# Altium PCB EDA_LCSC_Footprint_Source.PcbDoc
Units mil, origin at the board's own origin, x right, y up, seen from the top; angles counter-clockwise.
Board outline 4500 x 2500 mil, 2 copper layers (Top Layer, Bottom Layer), stack 62.2 mil thick; 64 components, 41 nets, 178 pads, 0 vias.
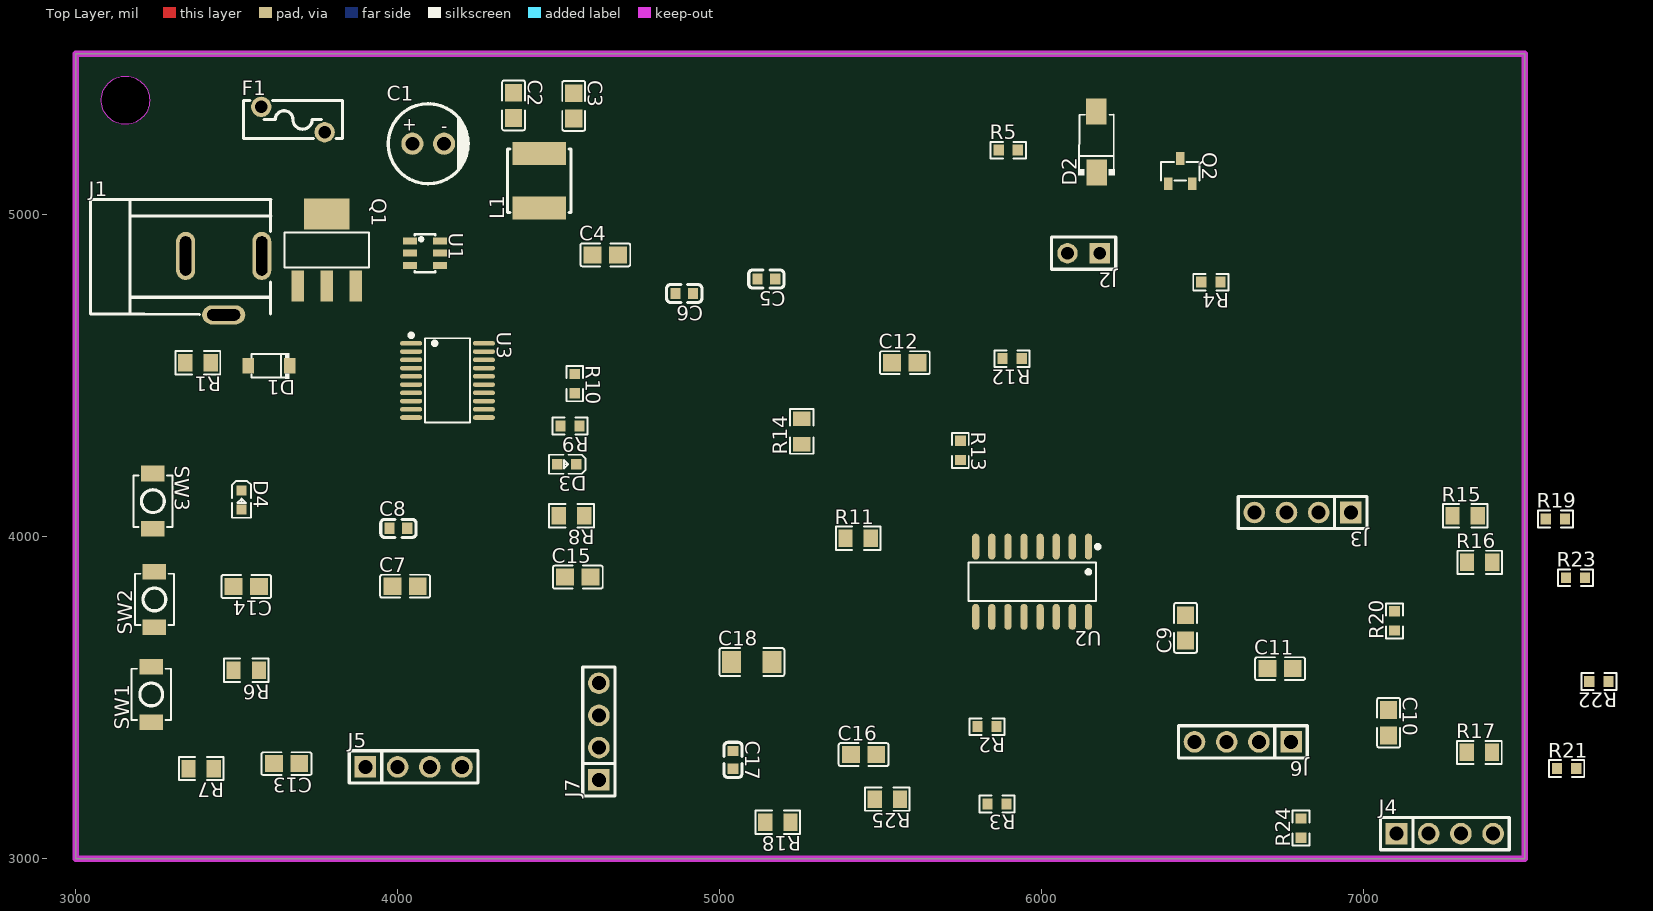
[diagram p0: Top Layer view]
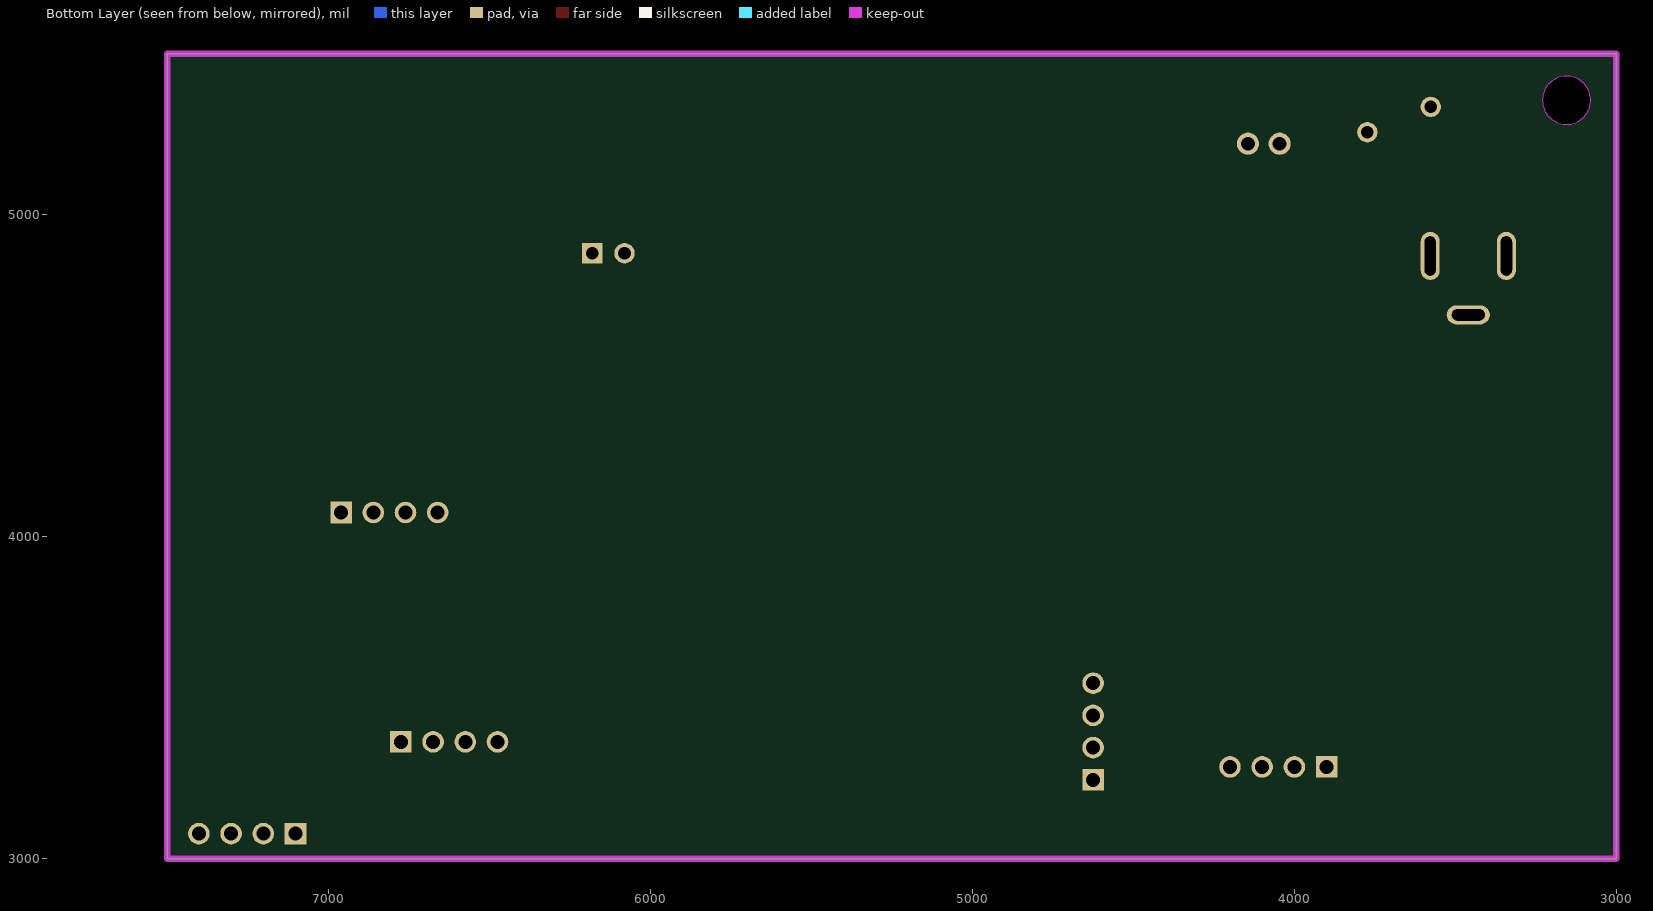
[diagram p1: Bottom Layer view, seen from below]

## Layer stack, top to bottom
Top Solder Mask Layer: solder mask 0.4, Dk 3.3
Top Layer: signal copper 1.4
Dielectric1: surface 59.4, FR4, Dk 4.5
Bottom Layer: signal copper 1.4
Bottom Solder Mask Layer: solder mask 0.4, Dk 3.3

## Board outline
3000,5500 3000,3000 7500,3000 7500,5500
cut-out: 3230,5355 3229.6,5347.3 3228.4,5339.7 3226.4,5332.2 3223.7,5325 3220.3,5318.1 3216.1,5311.5 3211.3,5305.5 3205.9,5300 3200,5295 3193.6,5290.7 3186.8,5287.1 3179.6,5284.2 3172.2,5282 3164.6,5280.6 3156.9,5280 3149.2,5280.2 3141.6,5281.2 3134,5283 3126.7,5285.5 3119.8,5288.8 3113.1,5292.8 3107,5297.4 3101.3,5302.7 3096.2,5308.5 3091.7,5314.7 3087.9,5321.5 3084.8,5328.5 3082.5,5335.9 3080.9,5343.5 3080.1,5351.1 3080.1,5358.9 3080.9,5366.5 3082.5,5374.1 3084.8,5381.5 3087.9,5388.5 3091.7,5395.3 3096.2,5401.5 3101.3,5407.3 3107,5412.6 3113.1,5417.2 3119.8,5421.2 3126.7,5424.5 3134,5427 3141.6,5428.8 3149.2,5429.8 3156.9,5430 3164.6,5429.4 3172.2,5428 3179.6,5425.8 3186.8,5422.9 3193.6,5419.3 3200,5415 3205.9,5410 3211.3,5404.5 3216.1,5398.5 3220.3,5391.9 3223.7,5385 3226.4,5377.8 3228.4,5370.3 3229.6,5362.7

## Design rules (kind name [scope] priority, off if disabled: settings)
BoardOutlineClearance copperThickness1oz [All] p0: genericclearance=10 ignorepadtopadclearanceinfootprint=FALSE except(0: Arc-SplitContinuation Track-SplitContinuation SMDPad-SplitContinuation THPad-SplitContinuation Via-SplitContinuation Fill-SplitContinuation Poly-SplitContinuation Region-SplitContinuation Text-SplitContinuation)
BoardOutlineClearance copperThickness2oz [All] p0: genericclearance=10 ignorepadtopadclearanceinfootprint=FALSE except(0: Arc-SplitContinuation Track-SplitContinuation SMDPad-SplitContinuation THPad-SplitContinuation Via-SplitContinuation Fill-SplitContinuation Poly-SplitContinuation Region-SplitContinuation Text-SplitContinuation)
BoardOutlineClearance Plane_innerPlane [All] p0: genericclearance=10 ignorepadtopadclearanceinfootprint=FALSE except(0: Arc-SplitContinuation Track-SplitContinuation SMDPad-SplitContinuation THPad-SplitContinuation Via-SplitContinuation Fill-SplitContinuation Poly-SplitContinuation Region-SplitContinuation Text-SplitContinuation)
BoardOutlineClearance Copper_copperRegion [All] p0: genericclearance=10 ignorepadtopadclearanceinfootprint=FALSE except(0: Arc-SplitContinuation Track-SplitContinuation SMDPad-SplitContinuation THPad-SplitContinuation Via-SplitContinuation Fill-SplitContinuation Poly-SplitContinuation Region-SplitContinuation Text-SplitContinuation)
BoardOutlineClearance otherClearance [All] p0: genericclearance=10 ignorepadtopadclearanceinfootprint=FALSE except(0: Arc-SplitContinuation Track-SplitContinuation SMDPad-SplitContinuation THPad-SplitContinuation Via-SplitContinuation Fill-SplitContinuation Poly-SplitContinuation Region-SplitContinuation Text-SplitContinuation)
Clearance copperThickness1oz [All] p1: gap=7 ignorepadtopadclearanceinfootprint=FALSE
Clearance copperThickness2oz [All] p1: gap=7 ignorepadtopadclearanceinfootprint=FALSE
Clearance Plane_innerPlane [All] p1: gap=7 ignorepadtopadclearanceinfootprint=FALSE
Clearance Copper_copperRegion [All] p1: gap=7 ignorepadtopadclearanceinfootprint=FALSE
Clearance otherClearance [All] p1: gap=7 ignorepadtopadclearanceinfootprint=FALSE
DiffPairsRouting differentialPair [All] p1: maxuncoupledlength=10 minlimit=5.9843 maxlimit=Infinity mostfreqgap=5.9843 toplayer_minwidth=5 toplayer_prefwidth=10 toplayer_maxwidth=100 bottomlayer_minwidth=5 bottomlayer_prefwidth=10 bottomlayer_maxwidth=100
PasteMaskExpansion pasteMaskExpansion [All] p1: expansion=0
PlaneConnect innerPlane [All] p1: planeconnectstyle=Relief reliefexpansion=20 reliefentries=4 reliefconductorwidth=10 reliefairgap=10
PolygonConnect copperRegion [All] p1: connectstyle=Relief reliefentries=4 reliefconductorwidth=10 polygonreliefangle="90 Angle" airgapwidth=10
RoutingVias viaSize [All] p1: viastyle="Through Hole" holewidth=12.0078 minholewidth=11.811 maxholewidth=248.0314 width=12.0078 minwidth=11.811 maxwidth=248.0314
SolderMaskExpansion solderMaskExpansion [IsVia] p1: useseparateexpansions=TRUE expansion=-1000 expansionbottom=-1000
SolderMaskExpansion solderMaskExpansion [All] p2: useseparateexpansions=TRUE expansion=2.0079 expansionbottom=2.0079
Width copperThickness1oz [All] p1: maxlimit=100 minlimit=5 preferedwidth=10
Width copperThickness2oz [All] p1: maxlimit=100 minlimit=8 preferedwidth=10

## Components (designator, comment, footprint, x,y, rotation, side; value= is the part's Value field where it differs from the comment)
C1 "47uF" CAP-TH_BD6.3-P2.50-D0.6-FD 4095,5220 r0 top
C2 "10uF" C0805#1 4360.2,5338.9 r270 top
C3 "100nF" C0805#1 4546.9,5337.5 r270 top
C4 "100nF" C0805#2 4645,4875 r0 top
C5 "22uF" C0603#1 5145,4800 r180 top
C6 "22uF" C0603#1 4890,4755 r180 top
C7 "100nF" C0805#2 4023.1,3846 r0 top
C8 "4.7uF" C0603#2 4002.5,4025.6 r0 top
C9 "100nF" C0805#2 6446.6,3716.6 r90 top
C10 "100nF" C0805#3 7077.1,3422.3 r270 top
C11 "100nF" C0805#2 6740,3590 r0 top
C12 "100nF" C0805#2 5575,4540 r0 top
C13 "100nF" C0805#2 3655,3295 r180 top
C14 "100nF" C0805#2 3530,3845 r180 top
C15 "100nF" C0805#3 4559.6,3874.5 r0 top
C16 "100nF" C0805#2 5446.9,3323.1 r0 top
C17 "10uF" C0603#2 5041.5,3306.8 r270 top
C18 "220uF" C1206 5099.9,3610.6 r0 top
D1 "BZT52C10" SOD-123_L2.7-W1.6-LS3.7-RD 3600,4530 r180 top
D2 "SS16" SMA_L4.3-W2.6-LS5.0-RD 6170,5225 r90 top
D3 "FC-1608G1-520" LED0603-RD 4525,4225 r180 top
D4 "XL-1608SURC-06" LED0603-RD_RED 3515.3,4113.6 r270 top
F1 "RL60-050" FUSE-TH_L7.8-W3.0-P5.10-D0.5-S2.00 3675,5295 r0 top
J1 "DC005-T25" DC-IN-TH_DC-005-20A-1 3460,4780 r0 top
J2 "LAIL-PZ2.54-2P-L" CONN-TH_LAIL-PZ2.54-2P-L 6130,4880 r180 top
J3 "HX PZ2.54-1x4P ZZ" HDR-TH_4P-P2.54-V-M 6810,4075 r180 top
J4 "HX PZ2.54-1x4P ZZ" HDR-TH_4P-P2.54-V-M 7251.6,3077.8 r0 top
J5 "HX PZ2.54-1x4P ZZ" HDR-TH_4P-P2.54-V-M 4050,3285 r0 top
J6 "HX PZ2.54-1x4P ZZ" HDR-TH_4P-P2.54-V-M 6624.4,3362.8 r180 top
J7 "HX PZ2.54-1x4P ZZ" HDR-TH_4P-P2.54-V-M 4625,3395 r90 top
L1 "3.9uH" IND-SMD_L5.0-W5.0_FNR50XXS 4440,5105 r90 top
Q1 "DMP6023LE-13" SOT-223-4_L6.5-W3.5-P2.30-LS7.0-BR 3780,4890 r270 top
Q2 "AO3400A" SOT-23-3_L2.9-W1.3-P1.90-LS2.4-BR 6430,5135 r270 top
R1 "47kΩ" R0805 3380,4540 r180 top
R2 "1kΩ" R0603#1 5830,3410 r180 top
R3 "1kΩ" R0603#2 5861,3169.9 r180 top
R4 "1kΩ" R0603#1 6525,4790 r180 top
R5 "100kΩ" R0603#2 5896,5200 r0 top
R6 "10kΩ" R0805 3530,3585 r180 top
R7 "10kΩ" R0805 3390,3280 r180 top
R8 "10kΩ" R0805 4540,4065 r180 top
R9 "1kΩ" R0603#2 4535.2,4343.3 r180 top
R10 "1kΩ" R0603#1 4550,4475 r270 top
R11 "10kΩ" R0805 5430,3995 r0 top
R12 "100kΩ" R0603#2 5907.9,4552.5 r180 top
R13 "100kΩ" R0603#1 5747.4,4267.9 r270 top
R14 "10kΩ" R0805 5254.6,4326.7 r90 top
R15 "10kΩ" R0805 7315,4065 r0 top
R16 "10kΩ" R0805 7360,3920 r0 top
R17 "10kΩ" R0805 7358.9,3330 r0 top
R18 "10kΩ" R0805 5180.6,3113.1 r180 top
R19 "1kΩ" R0603#1 7595,4055 r0 top
R20 "1kΩ" R0603#3 7095.6,3738.5 r90 top
R21 "1kΩ" R0603#1 7630,3280 r0 top
R22 "1kΩ" R0603#1 7730,3550 r180 top
R23 "1kΩ" R0603#3 7657.2,3872.4 r0 top
R24 "1kΩ" R0603#1 6805,3095 r90 top
R25 "10kΩ" R0805 5520.6,3185 r180 top
SW1 "TS-1088-AR02016" SW-SMD_L3.9-W3.0-P4.45 3235,3510 r90 top
SW2 "TS-1088-AR02016" SW-SMD_L3.9-W3.0-P4.45 3245,3805 r90 top
SW3 "TS-1088-AR02016" SW-SMD_L3.9-W3.0-P4.45 3240,4110 r270 top
U1 "AP63203WU-7" TSOT-26_L2.9-W1.6-P0.95-LS2.8-BL 4085,4880 r270 top
U2 "74HC4052D,652" SO-16_L9.9-W3.9-P1.27-LS6.0-BL 5970,3860 r180 top
U3 "STM32G030F6P6" TSSOP-20_L6.5-W4.4-P0.65-LS6.4-BL 4155,4485 r270 top

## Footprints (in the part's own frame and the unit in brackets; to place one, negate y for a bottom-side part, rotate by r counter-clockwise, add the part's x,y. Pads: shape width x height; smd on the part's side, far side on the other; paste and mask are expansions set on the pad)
C0603#1 [mil]
  rect 31.5x35.4 smd: 1(-27.6,0) 2(27.6,0)
  silkscreen extent -55,-28 55,28
C0603#2 [mil]
  rect 31.5x35.4 smd: 1(-27.5,0) 2(27.6,0)
  silkscreen extent -55,-28 55,28
C0805#1 [mil]
  rect 55.5x53.1 smd paste-3937 mask+2: 1(-39.4,0) 2(39.3,0)
  silkscreen extent -77,-36 77,36
C0805#2 [mil]
  rect 55.5x53.1 smd paste-3937 mask+2: 1(-39.4,0) 2(39.4,0)
  silkscreen extent -77,-36 77,36
C0805#3 [mil]
  rect 55.5x53.1 smd paste-3937 mask+2: 1(-39.3,0) 2(39.4,0)
  silkscreen extent -77,-36 77,36
C1206 [mil]
  rect 58.5x68 smd paste-3937 mask+2: 1(-62.7,0) 2(62.7,0)
  silkscreen extent -101,-43 101,43
CAP-TH_BD6.3-P2.50-D0.6-FD [mil]
  round 68.9 hole 43.3 paste+0 mask+2: 1(-49.2,0) 2(49.2,0)
  silkscreen extent -124,-124 126,124
CONN-TH_LAIL-PZ2.54-2P-L [mil]
  rect 63x63 hole 39.4 paste+0 mask+2: 1(-50,0)
  round 63 hole 39.4 paste+0 mask+2: 2(50,0)
  silkscreen extent -100,-50 100,50
DC-IN-TH_DC-005-20A-1 [mil]
  oval 59.1x149.6 hole 35.4 slot 122.1 at 90 deg: 1(118.2,91.5) 2(-118.1,91.5)
  oval 133.9x59.1 hole 35.4 slot 102.4 at 0 deg: 3(0,-91.5)
  silkscreen extent -414,-90 146,267
FUSE-TH_L7.8-W3.0-P5.10-D0.5-S2.00 [mil]
  round 63 hole 39.4: 1(-98.4,39.4) 2(98.4,-39.4)
  silkscreen extent -154,-59 154,59
HDR-TH_4P-P2.54-V-M [mil]
  rect 66.9x66.9 hole 43.3: 1(-150,0)
  round 66.9 hole 43.3: 2(-50,0) 3(50,0) 4(150,0)
  silkscreen extent -200,-50 200,50
IND-SMD_L5.0-W5.0_FNR50XXS [mil]
  rect 70.9x165.4 smd: 1(-84.6,0) 2(84.6,0)
  silkscreen extent -98,-98 98,98
LED0603-RD [mil]
  rect 31.5x31.5 smd: 1(-29.5,0) 2(29.5,0)
  silkscreen extent -59,-29 55,30
LED0603-RD_RED [mil]
  rect 31.5x31.5 smd: 1(-29.5,-0.1) 2(29.5,0.2)
  silkscreen extent -59,-29 55,30
R0603#1 [mil]
  rect 31.8x34 smd paste-3937 mask+2: 1(-29.7,0) 2(29.7,0)
  silkscreen extent -54,-26 54,26
R0603#2 [mil]
  rect 31.8x34 smd paste-3937 mask+2: 1(-29.7,0) 2(29.6,0)
  silkscreen extent -55,-26 54,26
R0603#3 [mil]
  rect 31.8x34 smd paste-3937 mask+2: 1(-29.6,0) 2(29.7,0)
  silkscreen extent -54,-26 54,26
R0805 [mil]
  rect 44.6x54.2 smd paste-3937 mask+2: 1(-39.4,0) 2(39.4,0)
  silkscreen extent -69,-36 69,36
SMA_L4.3-W2.6-LS5.0-RD [mil]
  rect 80.6x63.8 smd: 1(-94.6,-0.4) 2(94.6,0.4)
  silkscreen extent -103,-57 85,57
SO-16_L9.9-W3.9-P1.27-LS6.0-BL [mil]
  oval 22.6x80.2 smd: 1(-175,-109) 2(-125,-109) 3(-75,-109) 4(-25,-109) 5(25,-109) 6(75,-109) 7(125,-109) 8(175,-109) 9(175,109) 10(125,109) 11(75,109) 12(25,109) 13(-25,109) 14(-75,109) 15(-125,109) 16(-175,109)
  silkscreen extent -210,-115 198,60
SOD-123_L2.7-W1.6-LS3.7-RD [mil]
  rect 35.8x48 smd: 1(-64.4,0) 2(64.4,0)
  silkscreen extent -63,-40 54,39
SOT-23-3_L2.9-W1.3-P1.90-LS2.4-BR [mil]
  rect 39.4x25.6 smd: 1(39.4,-37.4) 2(39.4,37.4) 3(-39.4,0)
  silkscreen extent -29,-60 29,60
SOT-223-4_L6.5-W3.5-P2.30-LS7.0-BR [mil]
  rect 97.2x38.6 smd: 1(111.6,-90.6) 2(111.6,0) 3(111.6,90.6)
  rect 97.2x141.7 smd: 4(-111.6,0)
  silkscreen extent -54,-131 54,131
SW-SMD_L3.9-W3.0-P4.45 [mil]
  rect 48.4x73.2 smd: 1(-86,0) 2(86,0)
  silkscreen extent -80,-61 80,61
TSOT-26_L2.9-W1.6-P0.95-LS2.8-BL [mil]
  rect 21.7x43.3 smd paste+0 mask+2: 1(-37.4,-47.2) 2(0,-47.2) 3(37.4,-47.2) 4(37.4,47.2) 5(0,47.2) 6(-37.4,47.2)
  silkscreen extent -59,-32 59,32
TSSOP-20_L6.5-W4.4-P0.65-LS6.4-BL [mil]
  oval 14.3x68.6 smd: 1(-115.2,-113) 2(-89.6,-113) 3(-64,-113) 4(-38.4,-113) 5(-12.8,-113) 6(12.8,-113) 7(38.4,-113) 8(64,-113) 9(89.6,-113) 10(115.2,-113) 11(115.2,113) 12(89.6,113) 13(64,113) 14(38.4,113) 15(12.8,113) 16(-12.8,113) 17(-38.4,113) 18(-64,113) 19(-89.6,113) 20(-115.2,113)
  silkscreen extent -146,-119 131,70

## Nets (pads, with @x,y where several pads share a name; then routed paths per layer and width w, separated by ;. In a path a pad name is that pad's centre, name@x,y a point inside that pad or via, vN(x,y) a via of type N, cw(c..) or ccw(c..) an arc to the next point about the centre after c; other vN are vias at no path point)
$1N171: F1.1 J1.1
$1N175: F1.2 Q1.2 Q1.4
$1N192: D1.2 Q1.1 R1.1
$1N448: C4.1 U1.6
$1N450: C4.2 L1.1 U1.5
$1N997: Q2.1 R4.2 R5.1
$1N1011: D2.2 J2.2 Q2.3
$1N1973: J7.3 R2.2 R25.2
$1N1982: J7.4 R3.2
$1N2020: D3.2 R9.2
$1N2028: D4.2 R10.2
$1N3740: J3.3 R15.2 R19.2
$1N3749: J3.4 R20.2
$1N3768: J4.3 R16.2 R21.2
$1N3777: J4.4 R22.2
$1N3796: J6.3 R17.2 R23.2
$1N3805: J6.4 R24.2
+3V3: C5.1 C6.1 C7.1 C8.1 C9.1 C10.1 C11.1 C12.1 C16.1 C17.1 C18.1 J3.1 J4.1 J5.1 J6.1 J7.1 L1.2 R6.1 R7.1 R8.1 R11.1 R14.1 R15.1 R16.1 R17.1 R18.1 R25.1 U1.1 U2.16 U3.4
AUX_RX_MUX: R21.1 U2.14
AUX_TX_MUX: R22.1 U2.5
GND: C1.2 C2.2 C3.2 C5.2 C6.2 C7.2 C8.2 C9.2 C10.2 C11.2 C12.2 C13.2 C14.2 C15.2 C16.2 C17.2 C18.2 D3.1 D4.1 J1.2 J3.2 J4.2 J5.3 J6.2 J7.2 Q2.2 R1.2 R5.2 R12.2 R13.2 SW1.2 SW2.2 SW3.2 U1.4 U2.7 U2.8 U3.5
KEY_AUTO: C13.1 R6.2 SW1.1 U3.16
KEY_MANUAL: C14.1 R7.2 SW2.1 U3.12
LED_FAULT: R10.1 U3.14
LED_STATUS: R9.1 U3.13
MAIN_RX_MUX: R19.1 U2.12
MAIN_TX_MUX: R20.1 U2.1
MUX_E: R11.2 U2.6 U3.7
MUX_S0: R12.1 U2.10 U3.2
MUX_S1: R13.1 U2.9 U3.3
NRST: C15.1 R8.2 SW3.1 U3.6
PUMP_CMD: R4.1 U3.11
RES_RX_MUX: R23.1 U2.15
RES_TX_MUX: R24.1 U2.2
SENS_RX: R14.2 U2.3 U3.10
SENS_TX: U2.13 U3.9
SWCLK: J5.4 U3.19
SWDIO: J5.2 U3.18
VIN_P: C1.1 C2.1 C3.1 D1.1 D2.1 J2.1 Q1.3 U1.2 U1.3
WIFI_RX: R3.1 R18.2 U3.1
WIFI_TX: R2.1 U3.20
pads on no net: J1.3 U2.4 U2.11 U3.8 U3.15 U3.17

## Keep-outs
Board Outline Layer:
  region: 3230,5355 3229.6,5347.3 3228.4,5339.7 3226.4,5332.2 3223.7,5325 3220.3,5318.1 3216.1,5311.5 3211.3,5305.5 3205.9,5300 3200,5295 3193.6,5290.7 3186.8,5287.1 3179.6,5284.2 3172.2,5282 3164.6,5280.6 3156.9,5280 3149.2,5280.2 3141.6,5281.2 3134,5283 3126.7,5285.5 3119.8,5288.8 3113.1,5292.8 3107,5297.4 3101.3,5302.7 3096.2,5308.5 3091.7,5314.7 3087.9,5321.5 3084.8,5328.5 3082.5,5335.9 3080.9,5343.5 3080.1,5351.1 3080.1,5358.9 3080.9,5366.5 3082.5,5374.1 3084.8,5381.5 3087.9,5388.5 3091.7,5395.3 3096.2,5401.5 3101.3,5407.3 3107,5412.6 3113.1,5417.2 3119.8,5421.2 3126.7,5424.5 3134,5427 3141.6,5428.8 3149.2,5429.8 3156.9,5430 3164.6,5429.4 3172.2,5428 3179.6,5425.8 3186.8,5422.9 3193.6,5419.3 3200,5415 3205.9,5410 3211.3,5404.5 3216.1,5398.5 3220.3,5391.9 3223.7,5385 3226.4,5377.8 3228.4,5370.3 3229.6,5362.7
  region: 3230,5355 3229.6,5347.3 3228.4,5339.7 3226.4,5332.2 3223.7,5325 3220.3,5318.1 3216.1,5311.5 3211.3,5305.5 3205.9,5300 3200,5295 3193.6,5290.7 3186.8,5287.1 3179.6,5284.2 3172.2,5282 3164.6,5280.6 3156.9,5280 3149.2,5280.2 3141.6,5281.2 3134,5283 3126.7,5285.5 3119.8,5288.8 3113.1,5292.8 3107,5297.4 3101.3,5302.7 3096.2,5308.5 3091.7,5314.7 3087.9,5321.5 3084.8,5328.5 3082.5,5335.9 3080.9,5343.5 3080.1,5351.1 3080.1,5358.9 3080.9,5366.5 3082.5,5374.1 3084.8,5381.5 3087.9,5388.5 3091.7,5395.3 3096.2,5401.5 3101.3,5407.3 3107,5412.6 3113.1,5417.2 3119.8,5421.2 3126.7,5424.5 3134,5427 3141.6,5428.8 3149.2,5429.8 3156.9,5430 3164.6,5429.4 3172.2,5428 3179.6,5425.8 3186.8,5422.9 3193.6,5419.3 3200,5415 3205.9,5410 3211.3,5404.5 3216.1,5398.5 3220.3,5391.9 3223.7,5385 3226.4,5377.8 3228.4,5370.3 3229.6,5362.7
  lines w0.1: 3080.1,5351.1 3080.9,5343.5 3082.5,5335.9 3084.8,5328.5 3087.9,5321.5 3091.7,5314.7 3096.2,5308.5 3101.3,5302.7 3107,5297.4 3113.1,5292.8 3119.8,5288.8 3126.7,5285.5 3134,5283 3141.6,5281.2 3149.2,5280.2 3156.9,5280 3164.6,5280.6 3172.2,5282 3179.6,5284.2 3186.8,5287.1 3193.6,5290.7 3200,5295 3205.9,5300 3211.3,5305.5 3216.1,5311.5 3220.3,5318.1 3223.7,5325 3226.4,5332.2 3228.4,5339.7 3229.6,5347.3 3230,5355 3229.6,5362.7 3228.4,5370.3 3226.4,5377.8 3223.7,5385 3220.3,5391.9 3216.1,5398.5 3211.3,5404.5 3205.9,5410 3200,5415 3193.6,5419.3 3186.8,5422.9 3179.6,5425.8 3172.2,5428 3164.6,5429.4 3156.9,5430 3149.2,5429.8 3141.6,5428.8 3134,5427 3126.7,5424.5 3119.8,5421.2 3113.1,5417.2 3107,5412.6 3101.3,5407.3 3096.2,5401.5 3091.7,5395.3 3087.9,5388.5 3084.8,5381.5 3082.5,5374.1 3080.9,5366.5 3080.1,5358.9 3080.1,5351.1
  lines w20: 3000,3000 3000,5500 7500,5500 7500,3000 3000,3000

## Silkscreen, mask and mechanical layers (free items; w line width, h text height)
Mechanical Layer:
  lines w0.1: 3080.1,5351.1 3080.9,5343.5 3082.5,5335.9 3084.8,5328.5 3087.9,5321.5 3091.7,5314.7 3096.2,5308.5 3101.3,5302.7 3107,5297.4 3113.1,5292.8 3119.8,5288.8 3126.7,5285.5 3134,5283 3141.6,5281.2 3149.2,5280.2 3156.9,5280 3164.6,5280.6 3172.2,5282 3179.6,5284.2 3186.8,5287.1 3193.6,5290.7 3200,5295 3205.9,5300 3211.3,5305.5 3216.1,5311.5 3220.3,5318.1 3223.7,5325 3226.4,5332.2 3228.4,5339.7 3229.6,5347.3 3230,5355 3229.6,5362.7 3228.4,5370.3 3226.4,5377.8 3223.7,5385 3220.3,5391.9 3216.1,5398.5 3211.3,5404.5 3205.9,5410 3200,5415 3193.6,5419.3 3186.8,5422.9 3179.6,5425.8 3172.2,5428 3164.6,5429.4 3156.9,5430 3149.2,5429.8 3141.6,5428.8 3134,5427 3126.7,5424.5 3119.8,5421.2 3113.1,5417.2 3107,5412.6 3101.3,5407.3 3096.2,5401.5 3091.7,5395.3 3087.9,5388.5 3084.8,5381.5 3082.5,5374.1 3080.9,5366.5 3080.1,5358.9 3080.1,5351.1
